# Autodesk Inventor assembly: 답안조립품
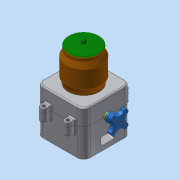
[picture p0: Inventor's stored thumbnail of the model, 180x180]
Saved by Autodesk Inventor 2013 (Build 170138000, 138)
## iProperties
Created: 2018-01
Part Number: 답안조립품
Document SubType Name: Assembly
Designer: dgall
Author: dgall
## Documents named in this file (9)
- C:\Users\dgall\Desktop\480107V1011\답안조립품.iam
- C:\Users\dgall\Desktop\480107V1011\본체.ipt
- C:\Users\dgall\Desktop\480107V1011\본체커버.ipt
- C:\Users\dgall\Desktop\480107V1011\볼트 M3x12.ipt
- C:\Users\dgall\Desktop\480107V1011\볼트 M4x12.ipt
- C:\Users\dgall\Desktop\480107V1011\용기.ipt
- C:\Users\dgall\Desktop\480107V1011\용기캡.ipt
- C:\Users\dgall\Desktop\480107V1011\핸들.ipt
- C:\Users\dgall\Desktop\480107V1011\핸들축.ipt
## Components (2 placed, 2 different names)
1. 핸들:1
2. 핸들축:1
